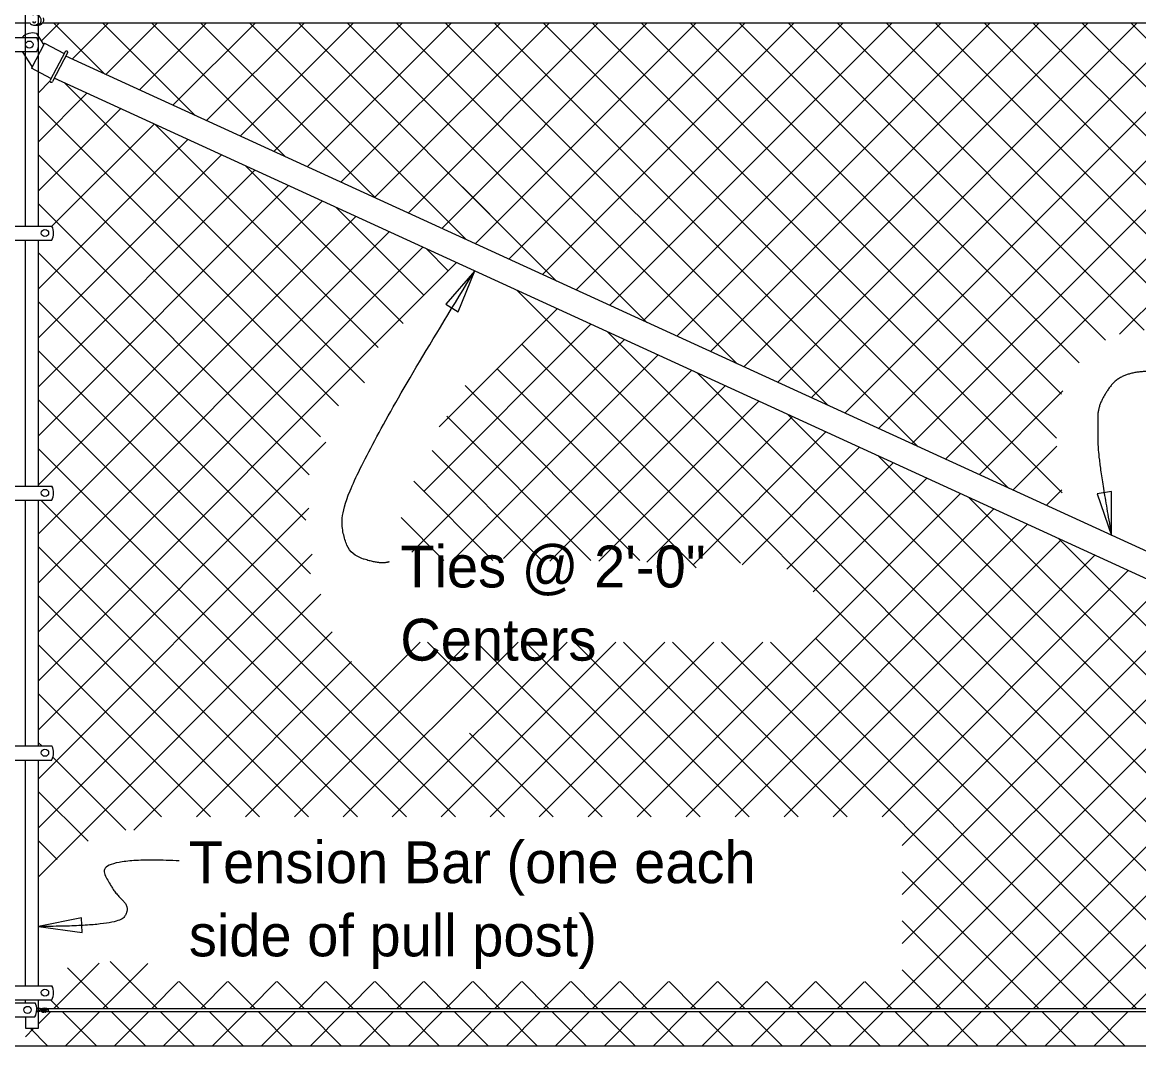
# Model space of a CAD drawing. Extents: x 0 to 41.1, y 0 to 26.4.
# Drawn here: x 12.4 to 17.77, y 17.47 to 22.39 of the extents above; entities that cross this region are included whole.
import ezdxf

# ---------------------------------------------------------------- set-up
doc = ezdxf.new("R2010")
doc.units = 0
for name, color, linetype in [('Dimension', 7, 'Continuous'), ('Miscellaneous', 7, 'Continuous'), ('SteelMisc', 7, 'Continuous'), ('SupstrConc', 7, 'Continuous'), ('TextStructures', 7, 'Continuous')]:
    doc.layers.add(name, color=color, linetype=linetype)

msp = doc.modelspace()

# ---------------------------------------------------------------- linework, layer by layer
at = {"layer": 'Dimension'}
for points in [[(14.5761, 21.1957), (14.4371, 21.0368), (14.4972, 20.9998)], [(17.6408, 19.9239), (17.6405, 20.1351), (17.5709, 20.1232)], [(12.4771, 18.0429), (12.6863, 18.0139), (12.6842, 18.0844)]]:
    msp.add_lwpolyline(points, close=True, dxfattribs=at)
for points in [[(14.1644, 19.7962), (14.1177, 19.782), (13.9347, 19.8493), (13.9433, 20.1759), (14.5761, 21.1958)], [(17.8509, 20.7118), (17.6943, 20.72), (17.5763, 20.5615), (17.5733, 20.4403), (17.578, 20.2726), (17.6407, 19.9238)], [(13.1545, 18.3586), (12.7557, 18.3765), (12.8361, 18.2097), (12.9224, 18.1322), (12.8539, 18.0428), (12.4771, 18.0428)]]:
    msp.add_open_spline(points, degree=2, dxfattribs=at)
at = {"layer": 'Miscellaneous'}
for p, q in [((12.4911, 22.303), (12.5782, 22.39)), ((12.5487, 22.39), (12.7955, 22.1432)), ((12.6389, 22.215), (12.8139, 22.39)), ((12.7844, 22.39), (13.2304, 21.944)), ((12.8005, 22.1409), (13.0496, 22.39)), ((12.9622, 22.0669), (13.2853, 22.39)), ((13.0201, 22.39), (13.6653, 21.7448)), ((13.1238, 21.9928), (13.521, 22.39)), ((13.2558, 22.39), (14.1002, 21.5456)), ((13.2855, 21.9188), (13.7567, 22.39)), ((13.4471, 21.8448), (13.9924, 22.39)), ((13.4916, 22.39), (14.5351, 21.3464)), ((13.6088, 21.7707), (14.2281, 22.39)), ((13.7273, 22.39), (14.9701, 21.1472)), ((13.7705, 21.6967), (14.4638, 22.39)), ((13.9321, 21.6226), (14.6995, 22.39)), ((13.963, 22.39), (15.405, 20.948)), ((14.0938, 21.5486), (14.9352, 22.39)), ((14.1987, 22.39), (15.8399, 20.7488)), ((14.2554, 21.4745), (15.1709, 22.39)), ((14.4171, 21.4005), (15.4066, 22.39)), ((14.4344, 22.39), (16.2748, 20.5496)), ((14.5787, 21.3264), (15.6423, 22.39)), ((14.6701, 22.39), (16.7097, 20.3504)), ((14.7404, 21.2524), (15.878, 22.39)), ((14.9021, 21.1784), (16.1137, 22.39)), ((14.9058, 22.39), (17.1446, 20.1512)), ((15.0637, 21.1043), (16.3494, 22.39)), ((15.1415, 22.39), (17.4036, 20.1279)), ((15.2254, 21.0303), (16.5851, 22.39)), ((15.3772, 22.39), (17.3758, 20.3914)), ((15.387, 20.9562), (16.8208, 22.39)), ((15.5487, 20.8822), (17.0565, 22.39)), ((15.6129, 22.39), (16.224, 21.7789)), ((15.7103, 20.8081), (17.2922, 22.39)), ((15.8486, 22.39), (16.224, 22.0146)), ((15.872, 20.7341), (17.5279, 22.39)), ((16.0337, 20.66), (17.7636, 22.39)), ((16.0843, 22.39), (17.6113, 20.8629)), ((16.1953, 20.586), (17.9993, 22.39)), ((16.32, 22.39), (17.7983, 20.9117)), ((16.357, 20.5119), (18.235, 22.39)), ((16.5186, 20.4379), (18.4707, 22.39)), ((16.5557, 22.39), (17.9778, 20.9679)), ((16.6803, 20.3639), (18.7064, 22.39)), ((16.7914, 22.39), (18.2135, 20.9679)), ((16.8419, 20.2898), (18.9421, 22.39)), ((17.0271, 22.39), (18.4492, 20.9679)), ((17.2628, 22.39), (18.6849, 20.9679)), ((17.4985, 22.39), (18.9206, 20.9679)), ((17.679, 20.8912), (19.1778, 22.39)), ((17.7342, 22.39), (19.1563, 20.9679)), ((12.4771, 22.0532), (12.532, 22.1081)), ((12.6041, 22.099), (14.0454, 20.6576)), ((12.4771, 21.8175), (12.71, 22.0505)), ((15.95, 22.0528), (17.4005, 20.6024)), ((16.1857, 22.0528), (17.4843, 20.7543)), ((12.4771, 21.9903), (13.9198, 20.5475)), ((12.4771, 21.5818), (12.8717, 21.9764)), ((12.5416, 21.4106), (13.0333, 21.9024)), ((13.0389, 21.8998), (14.1107, 20.8281)), ((12.4771, 21.1104), (13.195, 21.8283)), ((12.4771, 21.7546), (13.8345, 20.3972)), ((12.4771, 20.8747), (13.3567, 21.7543)), ((12.4771, 20.639), (13.5183, 21.6802)), ((13.4738, 21.7006), (14.2316, 20.9428)), ((12.4771, 20.4033), (13.68, 21.6062)), ((14.5173, 21.6), (14.649, 21.4683)), ((12.4771, 20.1676), (13.8416, 21.5322)), ((12.4771, 21.5189), (13.78, 20.2159)), ((13.9087, 21.5014), (14.3312, 21.0789)), ((12.4771, 19.9319), (14.0033, 21.4581)), ((12.4771, 19.6962), (14.165, 21.3841)), ((12.4771, 19.4605), (14.3266, 21.31)), ((12.4771, 21.2832), (13.7633, 19.997)), ((14.3436, 21.3022), (14.4491, 21.1968)), ((12.4771, 19.2248), (14.4883, 21.236)), ((14.7785, 21.103), (17.3305, 18.5511)), ((12.4771, 21.0475), (13.7861, 19.7384)), ((14.4052, 20.4458), (14.9733, 21.0138)), ((14.3305, 20.1354), (15.1349, 20.9398)), ((15.2134, 20.9039), (18.4687, 17.6486)), ((14.2734, 19.8426), (15.2966, 20.8658)), ((12.4771, 20.8118), (14.7187, 18.5701)), ((14.4778, 19.8113), (15.4582, 20.7917)), ((14.8026, 20.8432), (15.8555, 19.7904)), ((14.6848, 20.7254), (15.6418, 19.7684)), ((14.7149, 19.8127), (15.6199, 20.7177)), ((15.6483, 20.7047), (18.7044, 17.6486)), ((14.53, 20.6445), (15.3708, 19.8037)), ((14.9378, 19.7999), (15.7815, 20.6436)), ((17.0036, 20.2158), (17.4071, 20.6192)), ((12.4771, 20.5761), (14.483, 18.5701)), ((15.1731, 19.7995), (15.9432, 20.5696)), ((14.4418, 20.497), (15.1351, 19.8037)), ((15.4049, 19.7956), (16.1049, 20.4955)), ((16.0832, 20.5055), (18.9401, 17.6486)), ((15.6276, 19.7826), (16.2665, 20.4215)), ((12.4771, 18.9891), (13.8596, 20.3716)), ((12.4771, 20.3404), (14.2473, 18.5701)), ((14.3708, 20.3323), (14.8994, 19.8037)), ((15.8633, 19.7826), (16.4282, 20.3475)), ((17.1653, 20.1417), (17.3773, 20.3538)), ((16.0774, 19.761), (16.5898, 20.2734)), ((16.5181, 20.3063), (19.1758, 17.6486)), ((14.283, 20.1844), (14.6637, 19.8037)), ((16.2045, 19.6524), (16.7515, 20.1994)), ((12.4884, 20.0933), (14.0116, 18.5701)), ((16.1384, 19.3505), (16.9132, 20.1253)), ((16.953, 20.1071), (19.4115, 17.6486)), ((17.3269, 20.0677), (17.4014, 20.1422)), ((12.4771, 18.7534), (13.778, 20.0543)), ((15.5936, 18.5701), (17.0748, 20.0513)), ((14.2226, 20.0091), (14.428, 19.8037)), ((15.8293, 18.5701), (17.2365, 19.9772)), ((16.065, 18.5701), (17.3981, 19.9032)), ((17.3879, 19.9079), (19.6472, 17.6486)), ((12.4771, 19.869), (13.7759, 18.5701)), ((12.4771, 18.5177), (13.7936, 19.8342)), ((16.3007, 18.5701), (17.5598, 19.8292)), ((16.5364, 18.5701), (17.7215, 19.7551)), ((16.6339, 18.4318), (17.8831, 19.6811)), ((12.4771, 18.282), (13.8357, 19.6406)), ((12.4771, 19.6333), (13.5402, 18.5701)), ((16.2952, 19.5864), (18.233, 17.6486)), ((16.6339, 18.1961), (18.0448, 19.607)), ((16.6339, 17.9604), (18.2064, 19.533)), ((12.9361, 18.5053), (13.8901, 19.4593)), ((16.5577, 17.6486), (18.3681, 19.4589)), ((12.4771, 19.3976), (13.3045, 18.5701)), ((13.4723, 18.5701), (14.3131, 19.4109)), ((13.708, 18.5701), (14.5488, 19.4109)), ((13.9437, 18.5701), (14.7845, 19.4109)), ((14.1794, 18.5701), (15.0202, 19.4109)), ((14.3493, 19.4109), (15.1901, 18.5701)), ((14.4151, 18.5701), (15.2559, 19.4109)), ((14.585, 19.4109), (15.4258, 18.5701)), ((14.6508, 18.5701), (15.4916, 19.4109)), ((14.8207, 19.4109), (15.6615, 18.5701)), ((14.8865, 18.5701), (15.7274, 19.4109)), ((15.0564, 19.4109), (15.8972, 18.5701)), ((15.1222, 18.5701), (15.9631, 19.4109)), ((15.2921, 19.4109), (16.1329, 18.5701)), ((15.3579, 18.5701), (16.1988, 19.4109)), ((15.5278, 19.4109), (16.3686, 18.5701)), ((15.7635, 19.4109), (17.5259, 17.6486)), ((15.9992, 19.4109), (17.7616, 17.6486)), ((16.0143, 19.3958), (16.8591, 18.5511)), ((16.2168, 19.429), (17.0948, 18.5511)), ((16.2349, 19.4109), (17.9973, 17.6486)), ((16.7934, 17.6486), (18.5298, 19.3849)), ((13.2366, 18.5701), (13.9832, 19.3167)), ((17.0291, 17.6486), (18.6914, 19.3109)), ((17.2648, 17.6486), (18.8531, 19.2368)), ((12.4771, 19.1619), (13.0688, 18.5701)), ((17.5005, 17.6486), (19.0147, 19.1628)), ((17.7362, 17.6486), (19.1764, 19.0887)), ((14.5513, 18.9732), (14.9544, 18.5701)), ((12.4771, 18.9262), (12.4923, 18.9109)), ((12.5465, 18.8568), (12.897, 18.5062)), ((12.4771, 18.6905), (12.715, 18.4525)), ((12.4771, 18.4548), (12.5674, 18.3644)), ((16.6339, 18.3049), (17.2902, 17.6486)), ((16.6339, 18.0692), (17.0545, 17.6486)), ((12.5508, 17.6486), (12.7683, 17.8661)), ((12.6161, 17.8443), (12.8118, 17.6486)), ((12.7865, 17.6486), (13.0028, 17.8649)), ((12.8223, 17.8738), (13.0476, 17.6486)), ((16.6339, 17.8335), (16.8188, 17.6486)), ((13.0222, 17.6486), (13.1513, 17.7777)), ((13.1541, 17.7777), (13.2833, 17.6486)), ((13.2579, 17.6486), (13.387, 17.7777)), ((13.3898, 17.7777), (13.519, 17.6486)), ((13.4936, 17.6486), (13.6227, 17.7777)), ((13.6255, 17.7777), (13.7547, 17.6486)), ((13.7293, 17.6486), (13.8584, 17.7777)), ((13.8612, 17.7777), (13.9904, 17.6486)), ((13.965, 17.6486), (14.0941, 17.7777)), ((14.0969, 17.7777), (14.2261, 17.6486)), ((14.2007, 17.6486), (14.3298, 17.7777)), ((14.3326, 17.7777), (14.4618, 17.6486)), ((14.4364, 17.6486), (14.5655, 17.7777)), ((14.5683, 17.7777), (14.6975, 17.6486)), ((14.6721, 17.6486), (14.8012, 17.7777)), ((14.804, 17.7777), (14.9332, 17.6486)), ((14.9078, 17.6486), (15.0369, 17.7777)), ((15.0397, 17.7777), (15.1689, 17.6486)), ((15.1435, 17.6486), (15.2726, 17.7777)), ((15.2754, 17.7777), (15.4046, 17.6486)), ((15.3792, 17.6486), (15.5083, 17.7777)), ((15.5111, 17.7777), (15.6403, 17.6486)), ((15.6149, 17.6486), (15.744, 17.7777)), ((15.7468, 17.7777), (15.876, 17.6486)), ((15.8506, 17.6486), (15.9797, 17.7777)), ((15.9825, 17.7777), (16.1117, 17.6486)), ((16.0863, 17.6486), (16.2155, 17.7777)), ((16.2182, 17.7777), (16.3474, 17.6486)), ((16.322, 17.6486), (16.4503, 17.7768)), ((16.4539, 17.7777), (16.5831, 17.6486)), ((12.5351, 17.6896), (12.5761, 17.6486)), ((12.4771, 17.5748), (12.536, 17.6338)), ((12.5909, 17.6338), (12.7554, 17.4693)), ((12.6072, 17.4693), (12.7717, 17.6338)), ((12.8266, 17.6338), (12.9911, 17.4693)), ((12.8429, 17.4693), (13.0074, 17.6338)), ((13.0623, 17.6338), (13.2268, 17.4693)), ((13.0786, 17.4693), (13.2431, 17.6338)), ((13.298, 17.6338), (13.4625, 17.4693)), ((13.3143, 17.4693), (13.4788, 17.6338)), ((13.5337, 17.6338), (13.6982, 17.4693)), ((13.5501, 17.4693), (13.7145, 17.6338)), ((13.7694, 17.6338), (13.9339, 17.4693)), ((13.7858, 17.4693), (13.9502, 17.6338)), ((14.0051, 17.6338), (14.1696, 17.4693)), ((14.0215, 17.4693), (14.1859, 17.6338)), ((14.2408, 17.6338), (14.4053, 17.4693)), ((14.2572, 17.4693), (14.4216, 17.6338)), ((14.4765, 17.6338), (14.641, 17.4693)), ((14.4929, 17.4693), (14.6573, 17.6338)), ((14.7122, 17.6338), (14.8767, 17.4693)), ((14.7286, 17.4693), (14.893, 17.6338)), ((14.9479, 17.6338), (15.1124, 17.4693)), ((14.9643, 17.4693), (15.1287, 17.6338)), ((15.1836, 17.6338), (15.3481, 17.4693)), ((15.2, 17.4693), (15.3644, 17.6338)), ((15.4193, 17.6338), (15.5838, 17.4693)), ((15.4357, 17.4693), (15.6001, 17.6338)), ((15.655, 17.6338), (15.8195, 17.4693)), ((15.6714, 17.4693), (15.8359, 17.6338)), ((15.8907, 17.6338), (16.0552, 17.4693)), ((15.9071, 17.4693), (16.0716, 17.6338)), ((16.1264, 17.6338), (16.2909, 17.4693)), ((16.1428, 17.4693), (16.3073, 17.6338)), ((16.3621, 17.6338), (16.5266, 17.4693)), ((16.3785, 17.4693), (16.543, 17.6338)), ((16.5978, 17.6338), (16.7623, 17.4693)), ((16.6142, 17.4693), (16.7787, 17.6338)), ((16.8335, 17.6338), (16.998, 17.4693)), ((16.8499, 17.4693), (17.0144, 17.6338)), ((17.0692, 17.6338), (17.2337, 17.4693)), ((17.0856, 17.4693), (17.2501, 17.6338)), ((17.3049, 17.6338), (17.4694, 17.4693)), ((17.3213, 17.4693), (17.4858, 17.6338)), ((17.5406, 17.6338), (17.7051, 17.4693)), ((17.557, 17.4693), (17.7215, 17.6338)), ((12.4146, 17.5123), (12.455, 17.5528)), ((12.4362, 17.5528), (12.5197, 17.4693))]:
    msp.add_line(p, q, dxfattribs=at)
at = {"layer": 'SteelMisc'}
for p, q in [((12.4146, 21.4109), (12.4146, 22.5933)), ((12.4771, 21.4109), (12.4771, 22.5933)), ((12.352, 22.39), (12.4351, 22.39)), ((12.4978, 22.39), (21.9118, 22.39)), ((11.9439, 22.3192), (12.4686, 22.3192)), ((12.5028, 22.2852), (12.468, 22.3383)), ((11.9439, 22.2514), (12.4686, 22.2514)), ((12.4467, 22.1792), (12.3998, 22.2509)), ((12.5062, 22.2918), (12.4425, 22.1712)), ((12.5062, 22.2918), (12.6005, 22.2419)), ((12.6051, 22.2506), (12.5327, 22.1134)), ((12.617, 22.2443), (12.5445, 22.1072)), ((21.8588, 17.9919), (12.6088, 22.2288)), ((12.5368, 22.1214), (12.4425, 22.1712)), ((21.8028, 17.8858), (12.5526, 22.1225)), ((12.0505, 21.4109), (12.5416, 21.4109)), ((12.0505, 21.3433), (12.5408, 21.3433)), ((12.4146, 20.1609), (12.4146, 21.3433)), ((12.4771, 20.1609), (12.4771, 21.3433)), ((12.0505, 20.1609), (12.5416, 20.1609)), ((12.0505, 20.0933), (12.5408, 20.0933)), ((12.4146, 18.9109), (12.4146, 20.0933)), ((12.4771, 18.9109), (12.4771, 20.0933)), ((12.0505, 18.9109), (12.5416, 18.9109)), ((12.0505, 18.8433), (12.5408, 18.8433)), ((12.4146, 17.7573), (12.4146, 18.8433)), ((12.4771, 17.7573), (12.4771, 18.8433)), ((12.0505, 17.7573), (12.5416, 17.7573)), ((11.9524, 17.6757), (12.4602, 17.6757)), ((12.0505, 17.6896), (12.5408, 17.6896)), ((12.4146, 17.6757), (12.4146, 17.6896)), ((12.4771, 17.6518), (12.4771, 17.6896)), ((12.4676, 17.6532), (12.4941, 17.6488)), ((12.4681, 17.6481), (12.4941, 17.644)), ((12.4681, 17.6328), (12.5018, 17.6385)), ((12.4685, 17.6375), (12.4986, 17.6425)), ((12.4771, 17.6389), (12.4771, 17.6467)), ((12.4771, 17.5528), (12.4771, 17.6343)), ((12.5141, 17.6338), (21.9119, 17.6338)), ((12.5154, 17.6486), (21.8852, 17.6486)), ((11.9526, 17.6079), (12.4599, 17.6079)), ((12.4146, 17.6079), (12.4146, 17.5528)), ((12.4146, 17.5528), (12.4771, 17.5528))]:
    msp.add_line(p, q, dxfattribs=at)
for centre, start, end in [((12.6109, 22.2474), 332.149, 152.149), ((12.5384, 22.1102), 152.149, 332.149)]:
    msp.add_arc(centre, 0.00673, start, end, dxfattribs=at)
for centre, major_axis, ratio, start_param, end_param in [((12.4603, 22.4014), (-0.0295, 0), 0.957868, 2.287002, 5.15055), ((12.4779, 22.4042), (0.0249, 0), 0.957868, 5.476514, 6.65252), ((12.4572, 22.4013), (-0.0251, 0), 0.957868, 0.487549, 0.751829), ((12.4643, 22.4133), (-0.0391, 0), 0.957868, 0.863445, 1.149078), ((12.4558, 22.3967), (0.00795, 0), 0.957868, 3.283494, 6.243757), ((12.4569, 22.3945), (-0.0206, -0.0021), 0.798607, 1.063032, 2.96375), ((12.4704, 22.3945), (-0.0206, -0.0021), 0.798607, 1.113032, 1.956656), ((12.4765, 22.4002), (-0.0231, 0), 0.957868, 1.44404, 2.503632), ((12.4514, 22.27), (-0.0647, 0.0342), 0.957868, 4.95193, 6.011789), ((12.3994, 22.2851), (0.0776, 0), 0.957868, 5.810211, 6.75616), ((12.472, 21.3778), (0.0776, 0), 0.957868, 5.801046, 6.744962), ((12.472, 20.1278), (0.0776, 0), 0.957868, 5.800848, 6.744767), ((12.472, 18.8777), (0.0776, 0), 0.957868, 5.810211, 6.745158), ((12.472, 17.7241), (0.0776, 0), 0.957868, 5.800651, 6.745353), ((12.3909, 17.6421), (0.0776, 0), 0.957868, 5.803915, 6.752041), ((12.4993, 17.6387), (-0.0095, 0), 0.957868, 5.623869, 6.017994), ((12.4993, 17.6387), (-0.0095, 0), 0.957868, 0.252467, 1.247174), ((12.4953, 17.6395), (0.0115, -0.0041), 0.737732, 5.048267, 8.212701), ((12.4934, 17.6346), (0.00982, 0), 0.957868, 0.636815, 1.505671), ((12.4988, 17.637), (0.00301, 0), 0.957868, 2.989083, 5.497792), ((12.4994, 17.6392), (-0.00453, 0), 0.957868, 5.149727, 5.551998), ((12.501, 17.6403), (-0.00872, 0), 0.957868, 2.114937, 5.0803), ((12.4966, 17.6379), (0.00527, 0), 0.957868, 5.660961, 6.743457), ((12.4988, 17.637), (0.00301, 0), 0.957868, 6.243757, 6.781286), ((12.5071, 17.6399), (0.00944, 0), 0.957868, 4.319295, 6.652508), ((12.5076, 17.6408), (-0.00872, 0), 0.957868, 3.422117, 5.180096), ((12.5076, 17.6408), (-0.00503, 0), 0.92697, 1.789502, 4.651061), ((12.5123, 17.6353), (-0.0142, 0), 0.957868, 3.175145, 4.85532), ((12.5043, 17.6203), (0.0274, 0), 0.957868, 0.63108, 1.149654)]:
    msp.add_ellipse(centre, major_axis=major_axis, ratio=ratio, start_param=start_param, end_param=end_param, dxfattribs=at)
for centre, major_axis in [((12.4327, 22.2847), (-0.0178, 0)), ((12.5079, 21.3782), (-0.0177, 0)), ((12.5079, 20.1282), (-0.0177, 0)), ((12.5079, 18.8781), (-0.0177, 0)), ((12.5079, 17.7245), (-0.0177, 0)), ((12.4242, 17.6412), (-0.0178, 0))]:
    msp.add_ellipse(centre, major_axis=major_axis, ratio=0.957868, dxfattribs=at)
at = {"layer": 'SupstrConc'}
msp.add_line((12.3521, 17.4693), (18.8204, 17.4693), dxfattribs=at)

# ---------------------------------------------------------------- texts
at = {"layer": 'TextStructures'}
for s, p in [('Ties @ 2\'-0" ', (14.2179, 19.6734)), ('Centers', (14.2179, 19.3214)), ('Tension Bar (one each ', (13.2005, 18.2509)), ('side of pull post)', (13.2005, 17.8989))]:
    msp.add_text(s, height=0.2016, dxfattribs=at).set_placement(p)

doc.saveas('drawing.dxf')
